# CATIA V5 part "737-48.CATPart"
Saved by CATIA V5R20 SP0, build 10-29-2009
Part number: 737-48
Definition: NONE
Nomenclature: 737-48
Source: Unknown
Description: 737-48
Bounding box of the stored display mesh (mm): x -52 to 38, y -51.97 to 51.97, z -60 to 42
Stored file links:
  C:\Users\Utente\Desktop\IO LAVORO\3D X SITO CF\X SITO\737\737-48.CATPart
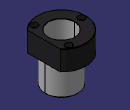
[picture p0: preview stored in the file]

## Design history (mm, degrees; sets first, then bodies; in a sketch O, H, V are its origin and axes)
Body1 "737-48" (main body)
  Solid1: solid without history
